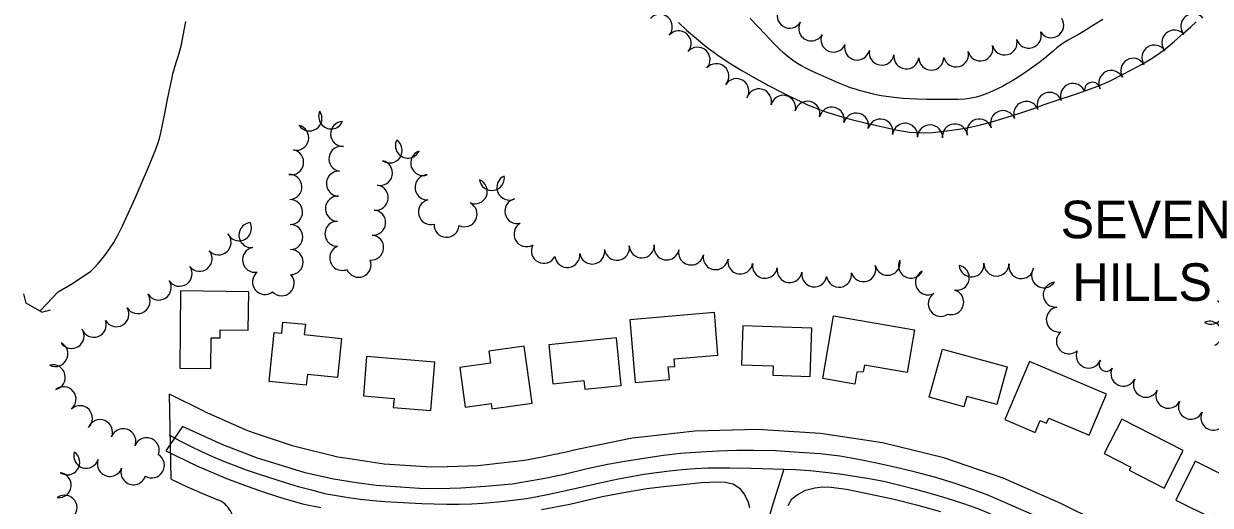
# Model space of a CAD drawing. Extents: x -25029 to 2274964, y -81170 to 687028.
# Drawn here: x -16157 to -15209, y -67607 to -67223 of the extents above; entities that cross this region are included whole.
import ezdxf

# ---------------------------------------------------------------- set-up
doc = ezdxf.new("R2010")
doc.units = 0
for name, color, linetype in [('81911BEA - RW_X_Fee_RW', 7, 'Continuous'), ('BLDG', 7, 'Continuous'), ('CITY-NAME', 7, 'Continuous'), ('CULVERT', 7, 'Continuous'), ('GE_X_CL_2000', 7, 'Continuous'), ('ROAD', 7, 'Continuous'), ('TREES', 7, 'Continuous'), ('WATER', 7, 'Continuous')]:
    doc.layers.add(name, color=color, linetype=linetype)

msp = doc.modelspace()

# ---------------------------------------------------------------- linework, layer by layer
at = {"layer": '81911BEA - RW_X_Fee_RW'}
for p in [(-16038.92, -67586.28), (-16012.23, -67532.37)]:
    msp.add_line(p, (-16040.16, -67518.56), dxfattribs=at)
for points in [[(-16012.23, -67532.37), (-15977.88, -67547.52), (-15971.84, -67549.57), (-15942.34, -67559.59), (-15905.88, -67568.48), (-15899.95, -67569.38), (-15868.77, -67574.12), (-15831.31, -67576.47), (-15818.01, -67576.13), (-15793.79, -67575.52), (-15756.49, -67571.26), (-15743.82, -67568.67), (-15719.72, -67563.74)], [(-15328.11, -67605.74), (-15374.09, -67585.45), (-15421.67, -67569.3), (-15470.49, -67557.4), (-15520.17, -67549.84), (-15524.29, -67549.58), (-15570.33, -67546.69), (-15620.56, -67547.97), (-15662.88, -67552.8), (-15670.49, -67553.67), (-15719.72, -67563.74)], [(-16038.92, -67586.28), (-16026.69, -67592.12), (-16014.3, -67597.62), (-16001.76, -67602.77)], [(-15989.37, -67626.99), (-15989.16, -67625.22), (-15988.95, -67623.45), (-15988.91, -67621.73), (-15989.15, -67619.99), (-15989.34, -67618.27), (-15989.68, -67616.58), (-15990.17, -67614.91), (-15990.8, -67613.3), (-15991.57, -67611.75), (-15992.47, -67610.27), (-15993.49, -67608.87), (-15994.63, -67607.57), (-15995.88, -67606.37), (-15997.22, -67605.28), (-15998.66, -67604.32), (-16000.18, -67603.48), (-16001.76, -67602.77)], [(-15202.63, -67667.84), (-15257.61, -67640.63), (-15324.83, -67607.36), (-15328.11, -67605.74)]]:
    msp.add_lwpolyline(points, dxfattribs=at)
at = {"layer": 'BLDG'}
for points in [[(-16032.13, -67497.8), (-16007.35, -67498.12), (-16007.04, -67473.43), (-15999.9, -67473.52), (-15999.81, -67467.1), (-15977.29, -67467.39), (-15976.9, -67436.72), (-16031.34, -67436.03)], [(-15668.12, -67509.14), (-15640.85, -67506.85), (-15641.7, -67496.74), (-15636.48, -67496.3), (-15636.97, -67490.4), (-15602.02, -67487.47), (-15604.88, -67453.38), (-15672.32, -67459.03)], [(-15906.08, -67505.2), (-15930.08, -67502.76), (-15930.96, -67511.44), (-15960.7, -67508.42), (-15956.72, -67469.29), (-15950.58, -67469.92), (-15949.67, -67460.9), (-15931.72, -67462.73), (-15932.55, -67470.96), (-15902.91, -67473.98)], [(-15444.95, -67467.05), (-15450.8, -67501.12), (-15484.94, -67495.26), (-15485.88, -67500.69), (-15490.95, -67500.95), (-15492.59, -67510.49), (-15518.3, -67506.07), (-15509.69, -67455.93)], [(-15583.27, -67495.13), (-15557.88, -67496), (-15558.13, -67503.39), (-15528.47, -67504.4), (-15527.15, -67465.74), (-15582.21, -67463.87)], [(-15785.16, -67484.1), (-15783.83, -67493.75), (-15808.31, -67497.12), (-15803.95, -67528.79), (-15783.37, -67525.96), (-15782.78, -67530.22), (-15750.6, -67525.79), (-15756.87, -67480.21)], [(-15734.04, -67510.16), (-15709.23, -67507.65), (-15708.53, -67514.63), (-15679.25, -67511.67), (-15683.1, -67473.61), (-15737.18, -67479.07)], [(-15885.33, -67519.95), (-15860.87, -67521.96), (-15861.46, -67529.2), (-15831.43, -67531.66), (-15828.26, -67492.88), (-15882.74, -67488.42)], [(-15379.31, -67526.83), (-15403.22, -67520.25), (-15405.52, -67528.63), (-15433.24, -67521), (-15422.68, -67482.6), (-15371.05, -67496.8)], [(-15372.73, -67538.78), (-15348.54, -67549.07), (-15344.51, -67539.58), (-15339.47, -67541.72), (-15337.71, -67537.59), (-15305.47, -67551.29), (-15291.56, -67518.55), (-15353.03, -67492.43)], [(-15293.49, -67565.89), (-15272.25, -67576.71), (-15273.5, -67579.17), (-15245.51, -67593.43), (-15230.23, -67563.44), (-15279.45, -67538.35)], [(-15236.26, -67603.03), (-15207.16, -67617.53), (-15205.55, -67614.29), (-15186.35, -67623.85), (-15172.54, -67596.11), (-15220.84, -67572.06)]]:
    msp.add_lwpolyline(points, close=True, dxfattribs=at)
at = {"layer": 'CULVERT'}
for p, q in [((-16154.68, -67445.81), (-16156.72, -67438.4)), ((-16142.38, -67453), (-16154.68, -67445.81)), ((-16142.38, -67453), (-16135.24, -67451.13))]:
    msp.add_line(p, q, dxfattribs=at)
at = {"layer": 'GE_X_CL_2000'}
for points in [[(-16040.53, -67551.09), (-16032.01, -67555.64), (-16023.4, -67560.01), (-16014.69, -67564.18), (-16005.9, -67568.17), (-15997.02, -67571.96), (-15988.07, -67575.56), (-15979.04, -67578.97), (-15968.73, -67582.5), (-15947.92, -67589.07), (-15937.45, -67592.11), (-15926.92, -67594.99), (-15916.35, -67597.7), (-15906.77, -67599.51), (-15897.17, -67601.07), (-15887.52, -67602.4), (-15877.84, -67603.47), (-15868.12, -67604.28), (-15858.41, -67604.86), (-15848.67, -67605.18), (-15838.7, -67605.79), (-15828.73, -67606.18), (-15818.74, -67606.35), (-15808.76, -67606.3), (-15798.77, -67606.04), (-15790, -67605.53), (-15781.24, -67604.82), (-15772.5, -67603.95), (-15763.77, -67602.9), (-15755.07, -67601.68), (-15746.39, -67600.28), (-15738.33, -67598.57), (-15716.45, -67593.86), (-15691.51, -67588.17), (-15681.46, -67586.05), (-15671.36, -67584.15), (-15661.23, -67582.45), (-15651.06, -67580.98), (-15640.86, -67579.73), (-15630.64, -67578.69), (-15620.4, -67577.87), (-15610.14, -67577.28), (-15592.63, -67577.34), (-15575.13, -67577.57), (-15549.44, -67578.26)], [(-15549.44, -67578.26), (-15558.49, -67607.22), (-15582.08, -67688.7), (-15603.84, -67764.46), (-15626.29, -67845.78), (-15645.38, -67912.89), (-15647.63, -67919.99), (-15649.68, -67927.14), (-15651.51, -67934.36), (-15653.14, -67941.62), (-15654.56, -67948.93), (-15655.77, -67956.27), (-15656.76, -67963.65), (-15657.54, -67971.05), (-15658.64, -67982.83), (-15659.5, -67994.64), (-15660.11, -68006.47), (-15660.47, -68018.31), (-15658.88, -68086.48), (-15656.14, -68233.78), (-15654.04, -68336.85), (-15652.89, -68423.01)], [(-15549.44, -67578.26), (-15540.13, -67578.57), (-15528.29, -67579.53), (-15516.47, -67580.73), (-15504.68, -67582.19), (-15492.92, -67583.88), (-15481.2, -67585.83), (-15469.53, -67588.02), (-15456.81, -67591.03), (-15444.17, -67594.3), (-15431.58, -67597.81), (-15419.07, -67601.56), (-15406.64, -67605.55), (-15394.28, -67609.8), (-15375.49, -67617.66), (-15356.83, -67625.82), (-15338.28, -67634.26), (-15319.87, -67642.98), (-15236.22, -67683.77), (-15175.19, -67714.38)]]:
    msp.add_lwpolyline(points, dxfattribs=at)
at = {"layer": 'ROAD'}
for points in [[(-15344.79, -67617.24), (-15374.58, -67604.13), (-15386.84, -67598.91), (-15398.6, -67594.72), (-15412.63, -67589.86), (-15427.83, -67585.06), (-15444.13, -67580.69), (-15456.12, -67577.82), (-15473.97, -67573.81), (-15489.62, -67570.69), (-15504.69, -67568.09), (-15520.49, -67566.06), (-15537.26, -67564.99), (-15556.07, -67563.82), (-15573.28, -67563.48), (-15587.27, -67563.59), (-15601.92, -67564.07), (-15616.07, -67564.7), (-15632.04, -67565.9), (-15645.53, -67567.56), (-15661.3, -67569.86), (-15676.4, -67572.31), (-15690.34, -67574.7), (-15706.62, -67578.24), (-15726.07, -67582.86), (-15741.69, -67586.04), (-15754.23, -67588.29), (-15766.41, -67590.4), (-15787.95, -67592.14), (-15807.59, -67593.54), (-15824.73, -67594.07), (-15840.48, -67593.74), (-15856.07, -67592.81), (-15875.03, -67591.36), (-15890.77, -67589.19), (-15909.35, -67586.42), (-15931.94, -67581.2), (-15949.92, -67575.79), (-15969.95, -67569.71), (-15997.7, -67558.88), (-16029.96, -67544.22), (-16043.22, -67563.68), (-16018.33, -67575.72), (-15994.75, -67585.71), (-15978.31, -67592.06), (-15963.7, -67596.93), (-15948.87, -67601.73), (-15932.79, -67606.31), (-15919.26, -67608.98)], [(-15742.9, -67610.71), (-15720.38, -67606.34), (-15694.48, -67600.3), (-15675.78, -67596.71), (-15658.76, -67593.76), (-15645.57, -67592.1), (-15629.66, -67590.6), (-15615.51, -67588.95), (-15602.76, -67588.46), (-15596.25, -67588.65), (-15589.88, -67590.09), (-15584.71, -67593.57), (-15581.01, -67598.43), (-15578.2, -67604.02), (-15576.77, -67609.08)], [(-15545.99, -67607.33), (-15543.02, -67602.15), (-15538.75, -67598.74), (-15532.06, -67595.2), (-15524.5, -67593.28), (-15518.2, -67592.6), (-15511.46, -67592.72), (-15499.31, -67594.27), (-15480.08, -67598.37), (-15461.29, -67602.46), (-15443.45, -67606.77), (-15424.15, -67612.11)]]:
    msp.add_lwpolyline(points, dxfattribs=at)
at = {"layer": 'TREES'}
for centre, radius, start, end in [((-15648.51, -67225.22), 10, 318.92691, 138.92691), ((-15544.74, -67216.25), 10, 148.65261, 328.65261), ((-15222.14, -67224.77), 10, 40.69542, 220.69542), ((-15527.54, -67226.46), 10, 149.94135, 329.94135), ((-15335.76, -67223.88), 10, 212.57513, 32.57513), ((-15633.43, -67238.36), 10, 318.92691, 138.92691), ((-15509.72, -67235.45), 10, 156.51734, 336.51734), ((-15372.98, -67237.62), 10, 193.85364, 13.85364), ((-15353.73, -67232.24), 10, 197.33202, 17.33202), ((-15237.3, -67237.81), 10, 40.69542, 220.69542), ((-15618.35, -67251.5), 10, 318.92691, 138.92691), ((-15490.81, -67241.74), 10, 166.67849, 346.67849), ((-15471.24, -67245.84), 10, 169.65921, 349.65921), ((-15411.82, -67247.19), 10, 193.81969, 13.81969), ((-15392.4, -67242.41), 10, 193.85364, 13.85364), ((-15253.28, -67249.76), 10, 32.88546, 212.88546), ((-15451.47, -67248.75), 10, 173.61231, 353.61231), ((-15431.53, -67249.72), 10, 180.81373, 0.81373), ((-15270.27, -67260.31), 10, 30.80297, 210.80297), ((-15603.27, -67264.64), 10, 318.92691, 138.92691), ((-15287.72, -67270.07), 10, 27.636, 207.636), ((-15587.29, -67276.58), 10, 327.56831, 147.56831), ((-15318.4, -67280.4), 10, 20.47566, 200.47566), ((-15302.81, -67275.8), 6.32, 9.99059, 189.99059), ((-15569.25, -67284.73), 10, 343.82283, 163.82283), ((-15549.93, -67289.88), 10, 346.30412, 166.30412), ((-15337.09, -67287.52), 10, 21.22233, 201.22233), ((-15530.5, -67294.62), 10, 346.30412, 166.30412), ((-15511.07, -67299.35), 10, 346.30412, 166.30412), ((-15374.33, -67302.13), 10, 21.51234, 201.51234), ((-15355.72, -67294.8), 10, 21.4917, 201.4917), ((-15928.47, -67298.31), 10, 214.47461, 34.47461), ((-15911.08, -67296.69), 10, 156.15516, 336.15516), ((-15901.6, -67310.73), 10, 91.88033, 271.88033), ((-15491.64, -67304.09), 10, 346.30412, 166.30412), ((-15472.21, -67308.82), 10, 346.30412, 166.30412), ((-15393.17, -67308.81), 10, 17.51296, 197.51296), ((-15938.96, -67313.71), 10, 257.01831, 77.01831), ((-15452.54, -67312.19), 10, 354.25672, 174.25672), ((-15432.6, -67313.52), 10, 358.1361, 178.1361), ((-15412.65, -67312.83), 10, 5.8136, 185.8136), ((-15902.89, -67330.59), 10, 80.7101, 260.7101), ((-15864.35, -67323.86), 10, 235.81925, 55.81925), ((-15849.77, -67320.01), 10, 153.72705, 333.72705), ((-15943.08, -67333.28), 10, 259.20881, 79.20881), ((-15837.57, -67333.9), 10, 108.86481, 288.86481), ((-15872.07, -67341.91), 10, 257.84611, 77.84611), ((-15944.49, -67353.09), 10, 272.64525, 92.64525), ((-15904.9, -67350.45), 10, 87.72046, 267.72046), ((-15834.07, -67353.36), 10, 91.50391, 271.50391), ((-15796.36, -67356.6), 10, 247.78018, 67.78018), ((-15782.69, -67345.84), 10, 188.6564, 8.6564), ((-15768.73, -67353.47), 10, 114.0208, 294.0208), ((-15875.45, -67361.6), 10, 262.71513, 82.71513), ((-15943.92, -67373.08), 10, 270.61951, 90.61951), ((-15905.7, -67370.43), 10, 87.72046, 267.72046), ((-15831.35, -67373.05), 10, 104.20552, 284.20552), ((-15804.53, -67374.84), 10, 243.93337, 63.93337), ((-15762.31, -67372.33), 10, 103.58168, 283.58168), ((-15877.52, -67381.49), 10, 265.36321, 85.36321), ((-15984.73, -67386.02), 10, 206.93111, 26.93111), ((-15974.79, -67391.44), 10, 95.89683, 275.89683), ((-15943.7, -67393.08), 10, 270.61951, 90.61951), ((-15906.04, -67390.43), 10, 90.3344, 270.3344), ((-15818.91, -67383.29), 10, 176.89462, 356.89462), ((-15754.99, -67390.72), 10, 119.81558, 299.81558), ((-16001.04, -67397.29), 10, 222.36183, 42.36183), ((-15879.14, -67401.42), 10, 265.36321, 85.36321), ((-16016.18, -67410.34), 10, 219.13093, 39.13093), ((-15971.94, -67411.22), 10, 100.50251, 280.50251), ((-15943.49, -67413.08), 10, 270.60937, 90.60937), ((-15902.22, -67409.69), 10, 112.08244, 292.08244), ((-15741.14, -67404), 10, 152.62796, 332.62796), ((-15722.34, -67407.35), 10, 187.1249, 7.1249), ((-15702.53, -67404.59), 10, 188.73537, 8.73537), ((-15682.76, -67401.56), 10, 188.73537, 8.73537), ((-15662.89, -67399.68), 10, 182.05711, 2.05711), ((-15643.1, -67401.33), 10, 168.39199, 348.39199), ((-15623.5, -67405.35), 10, 168.44486, 348.44486), ((-15889.2, -67415.17), 10, 202.24094, 22.24094), ((-15603.86, -67409.07), 10, 170.08303, 350.08303), ((-15584.16, -67412.52), 10, 170.08303, 350.08303), ((-15564.45, -67415.96), 10, 170.08303, 350.08303), ((-15466.53, -67413.58), 10, 192.28647, 12.28647), ((-15447.81, -67415.91), 10, 153.53122, 333.53122), ((-15399.45, -67414.81), 10, 185.08044, 5.08044), ((-15379.49, -67414.2), 10, 178.42213, 358.42213), ((-15359.64, -67416.2), 10, 170.03301, 350.03301), ((-16032.18, -67422.31), 10, 214.52028, 34.52028), ((-15963.99, -67428.96), 10, 127.75318, 307.75318), ((-15950.63, -67429.97), 10, 223.57538, 43.57538), ((-15544.75, -67419.41), 10, 170.08303, 350.08303), ((-15525.05, -67422.85), 10, 170.08303, 350.08303), ((-15505.32, -67423.06), 10, 188.68337, 8.68337), ((-15485.87, -67418.63), 10, 196.98555, 16.98555), ((-15434.23, -67429.23), 10, 117.58511, 297.58511), ((-15411.2, -67425.53), 10, 259.64528, 79.64528), ((-15341.5, -67423.51), 10, 146.0887, 326.0887), ((-16048.86, -67433.35), 10, 212.474, 32.474), ((-15332.17, -67439.04), 10, 95.8664, 275.8664), ((-16065.71, -67444.12), 10, 212.69036, 32.69036), ((-15423.98, -67446.37), 10, 124.19971, 304.19971), ((-15415.68, -67445), 10, 254.47602, 74.47603), ((-15208.13, -67452.62), 10, 238.641, 58.641), ((-16082.72, -67454.63), 10, 210.70361, 30.70361), ((-15329.68, -67458.88), 10, 98.47651, 278.47651), ((-16100.73, -67463.12), 10, 199.7729, 19.7729), ((-15209.19, -67470.26), 10, 294.47871, 114.47871), ((-16118.52, -67471.96), 10, 213.07946, 33.07946), ((-15321.61, -67476.28), 10, 131.28435, 311.28435), ((-16131.37, -67486.36), 10, 243.46256, 63.46256), ((-15305.77, -67487.61), 10, 157.55967, 337.55967), ((-15291.77, -67494.59), 5.7, 146.3669, 326.3669), ((-16133.49, -67505.03), 10, 283.53987, 103.53987), ((-15278.05, -67502.17), 10, 153.79095, 333.79095), ((-15260.09, -67510.97), 10, 153.97948, 333.97948), ((-16124.91, -67522.57), 10, 308.61167, 128.61167), ((-15242.12, -67519.74), 10, 153.97948, 333.97948), ((-16111.84, -67537.69), 10, 313.05602, 133.05602), ((-15224.15, -67528.52), 10, 153.97948, 333.97948), ((-16095.76, -67548.77), 10, 337.84106, 157.84106), ((-15206.18, -67537.29), 10, 153.97948, 333.97948), ((-16077.15, -67556.11), 10, 339.06586, 159.06586), ((-16058.48, -67563.28), 10, 338.93259, 158.93259), ((-16121.99, -67572.95), 10, 235.82096, 55.82096), ((-16106.84, -67567.68), 10, 162.49009, 342.49009), ((-16054.36, -67575.41), 10, 238.61356, 58.61356), ((-16087.92, -67574.15), 10, 159.77821, 339.77821), ((-16128.8, -67591.15), 10, 263.19024, 83.19024), ((-16069.05, -67580.78), 10, 161.51145, 341.51145), ((-16124.11, -67609.17), 10, 305.99443, 125.99443)]:
    msp.add_arc(centre, radius, start, end, dxfattribs=at)
at = {"layer": 'WATER'}
for points in [[(-16143.2, -67451.73), (-16129.19, -67436.68), (-16117.77, -67430.2), (-16103.06, -67420.26), (-16100.54, -67417.69), (-16097.27, -67414.16), (-16094.29, -67410.67), (-16091.25, -67406.8), (-16088.1, -67402.39), (-16084.86, -67397.33), (-16081.5, -67391.43), (-16077.72, -67384.02), (-16073.18, -67374.31), (-16067.73, -67362.05), (-16062.07, -67348.97), (-16057.12, -67337.32), (-16053.57, -67328.79), (-16051.21, -67322.85), (-16049.61, -67318.42), (-16048.37, -67314.42), (-16047.19, -67309.76), (-16045.81, -67303.34), (-16044.06, -67294.53), (-16042.13, -67284.63), (-16040.3, -67275.45), (-16038.78, -67268.31), (-16037.48, -67262.82), (-16036.21, -67258.14), (-16034.83, -67253.57), (-16033.4, -67248.96), (-16032.02, -67244.31), (-16030.73, -67239.3), (-16029.24, -67232.2), (-16027.22, -67220.98)], [(-15633.59, -67221.86), (-15627.04, -67227.91), (-15619.26, -67234.61), (-15610.8, -67241.4), (-15602.09, -67247.81), (-15592.95, -67253.95), (-15583.07, -67260.01), (-15572.36, -67266.13), (-15561.57, -67271.98), (-15551.67, -67277.15), (-15543.39, -67281.34), (-15536.48, -67284.67), (-15530.44, -67287.39), (-15524.83, -67289.71), (-15519.48, -67291.75), (-15514.27, -67293.59), (-15508.98, -67295.33), (-15502.89, -67297.15), (-15495.21, -67299.23), (-15485.54, -67301.64), (-15475.18, -67304.1), (-15465.87, -67306.22), (-15458.85, -67307.69), (-15453.56, -67308.64), (-15448.94, -67309.25), (-15444.03, -67309.69), (-15438.14, -67309.84), (-15430.69, -67309.52), (-15421.38, -67308.62), (-15411.21, -67307.26), (-15401.52, -67305.61), (-15393.29, -67303.82), (-15386.27, -67301.95), (-15379.86, -67300.07), (-15373.59, -67298.2), (-15367.5, -67296.34), (-15361.71, -67294.48), (-15356.15, -67292.55), (-15349.78, -67290.28), (-15341.36, -67287.34), (-15330.22, -67283.57), (-15318.08, -67279.5), (-15307.25, -67275.79), (-15299.34, -67272.9), (-15293.21, -67270.34), (-15287.02, -67267.4), (-15279.43, -67263.56), (-15271.09, -67259.2), (-15263.16, -67254.88), (-15256.45, -67250.98), (-15250.42, -67247.04), (-15244.22, -67242.39), (-15237.27, -67236.66), (-15230.28, -67230.58), (-15224.26, -67225.16), (-15219.99, -67221.21)], [(-15294.54, -67219.25), (-15301.94, -67224), (-15308.56, -67228.18), (-15314.05, -67231.37), (-15318.52, -67233.8), (-15322.24, -67235.84), (-15325.47, -67237.8), (-15328.41, -67239.85), (-15331.28, -67242.08), (-15334.25, -67244.57), (-15337.42, -67247.29), (-15340.87, -67250.16), (-15344.63, -67253.13), (-15348.7, -67256.18), (-15353.02, -67259.28), (-15357.54, -67262.38), (-15362.1, -67265.38), (-15366.54, -67268.15), (-15370.74, -67270.58), (-15374.74, -67272.73), (-15378.66, -67274.67), (-15382.55, -67276.45), (-15386.3, -67278.04), (-15389.77, -67279.39), (-15392.86, -67280.47), (-15395.65, -67281.3), (-15398.3, -67281.95), (-15401.07, -67282.46), (-15404.7, -67282.85), (-15410.09, -67283.1), (-15417.71, -67283.22), (-15426.57, -67283.22), (-15435.28, -67283.12), (-15442.74, -67282.93), (-15448.97, -67282.67), (-15454.31, -67282.33), (-15459.04, -67281.94), (-15463.38, -67281.46), (-15467.51, -67280.9), (-15471.59, -67280.23), (-15475.67, -67279.44), (-15479.78, -67278.52), (-15483.93, -67277.48), (-15488.07, -67276.33), (-15492.12, -67275.1), (-15496.11, -67273.78), (-15500.53, -67272.15), (-15505.95, -67269.95), (-15512.69, -67267.04), (-15519.92, -67263.82), (-15526.53, -67260.78), (-15531.69, -67258.3), (-15535.7, -67256.2), (-15539.11, -67254.15), (-15542.44, -67251.87), (-15545.85, -67249.25), (-15549.43, -67246.19), (-15553.23, -67242.66), (-15557.13, -67238.78), (-15560.97, -67234.75), (-15564.81, -67230.54), (-15569.55, -67225.41), (-15576.33, -67218.44)]]:
    msp.add_lwpolyline(points, dxfattribs=at)

# ---------------------------------------------------------------- texts
at = {"layer": 'CITY-NAME'}
for s, p in [('SEVEN', (-15328.2, -67394)), ('HILLS', (-15318.86, -67444))]:
    msp.add_text(s, height=30, dxfattribs=at).set_placement(p)

doc.saveas('drawing.dxf')
